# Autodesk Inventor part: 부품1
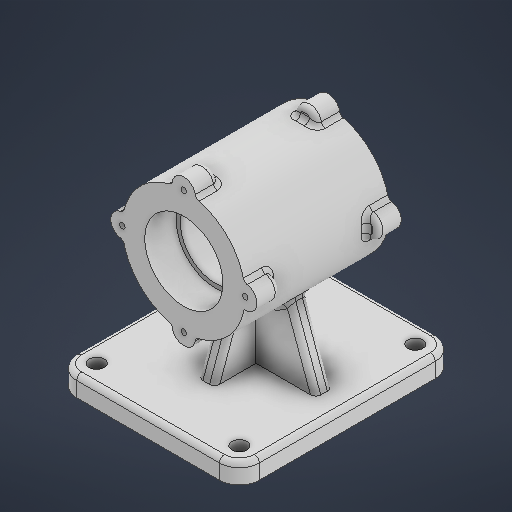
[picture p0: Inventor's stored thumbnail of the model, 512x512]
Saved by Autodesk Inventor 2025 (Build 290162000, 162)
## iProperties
Created: 2025-08
Part Number: 부품1
Material: 일반
Document SubType Name: Modeling
Designer: infra023
Density: 1 g/cm^3
Appearance: 기본값
Author: infra023
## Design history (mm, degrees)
sketch "스케치1"
  geometry: L1 (55, 65)-(-55, 65); L2 (-55, 65)-(-55, -65); L3 (-55, -65)-(55, -65); L4 (55, -65)-(55, 65); 3 further points
  constraints: 8 end point, 2 midpoint, 2 parallel, 1 horizontal, 1 horizontal alignment, 1 perpendicular, 1 vertical alignment
  dimensions: "d0" = 130 distance of L3.end L1.start; "d1" = 110 distance of L2.end L3.end
extrude "돌출1" new body sketch "스케치1" distance "d2" = 12; taper "d3" = 0 deg
fillet "모깎기1" dims "d4" = 12
sketch "스케치2"
  geometry: L1 (43, 53)-(-43, 53); L2 (-43, 53)-(-43, -53); L3 (-43, -53)-(43, -53); L4 (43, -53)-(43, 53); 3 further points
  constraints: 8 end point, 2 midpoint, 2 parallel, 1 horizontal, 1 horizontal alignment, 1 perpendicular, 1 vertical alignment
  dimensions: "d5" = 106 distance of L1.end L2.end; "d6" = 86 distance of L2.end L3.end
hole "구멍1" sketch "스케치2" at (43, 53), (43, -53), (-43, -53), (-43, 53) diameter "d7" = 9; stored, may be unused: countersink angle "d11" = 90 deg, drill point angle "d13" = 118 deg; dims "d8" = 6, "d9" = 4, "d10" = 2, "d12" = 8
sketch "스케치3"
  geometry: L1 (-12, -53)-(-12, 53) reference; L2 (-12, 0)-(70, 0); L3 (70, 0)-(70, -43.5); L4 (70, -43.5)-(107, -43.5); L5 (107, -43.5)-(107, 43.5); L6 (107, 43.5)-(70, 43.5); L7 (70, 0)-(70, 43.5); L8 (70, -43.5)-(91, -43.5); L9 (91, -24.5)-(91, 24.5); L10 (70, -43.5)-(93.5, -43.5); L11 (93.5, -43.5)-(93.5, -24.5); L12 (93.5, -24.5)-(70, -24.5); L13 (93.5, 43.5)-(93.5, 24.5); L14 (93.5, 24.5)-(70, 24.5); 2 further points
  constraints: 26 end point, 5 perpendicular, 5 point on line, 3 symmetric about line, 2 parallel, 1 horizontal, 1 midpoint, 1 vertical
  dimensions: "d14" = 82 distance of L2.start L2.end; "d15" = 43.5 distance of L2.end L3.end; "d16" = 37 distance of L3.end L4.end; "d17" = 87 distance of L4.end L5.end; "d18" = 21 distance of L3.end L8.end; "d19" = 23.5 distance of L3.end L10.end; "d20" = 19 distance of L10.end L11.end; "d21" = 16 distance between parallel lines of L5 L9
revolve "회전1" sketch "스케치3" stored, may be unused: angle "d22" = 90 deg
sketch "스케치4"
  geometry: L1 (0, 0)-(0, 37); L2 (0, 0)-(-37, 0); L3 (0, 0)-(37, 0); L4 (0, 0)-(0, -37); C1 r 21 at (0, 0) reference; C2 r 7 at (37, 0); C3 r 7 at (-37, 0); C4 r 7 at (0, 37); C5 r 7 at (0, -37); A1 r 37 centre (0, 0) between (0, 37) and (-37, 0) reference; 3 further points
  constraints: 8 end point, 4 centre point, 4 coincident, 4 point on circle, 2 horizontal, 2 vertical
  dimensions: "d23" = 14 diameter of C2; "d24" = 14 diameter of C3; "d25" = 14 diameter of C4; "d26" = 14 diameter of C5
sketch "스케치5"
  geometry: C1 r 7 at (0, 37) reference; C2 r 7 at (-37, 0) reference; C3 r 7 at (37, 0) reference; C4 r 7 at (0, -37) reference; 1 further point
extrude "돌출2" join sketch "스케치4" distance "d27" = 14; taper "d28" = 0 deg
extrude "돌출3" join sketch "스케치5" distance "d29" = 14; taper "d30" = 0 deg
fillet "모깎기2" dims "d31" = 3
fillet "모깎기3" dims "d32" = 3
fillet "모깎기4" dims "d33" = 3
sketch "스케치6"
  geometry: L1 (-37, -37)-(0, -37); C1 r 7 at (-37, -37); A1 r 7 centre (-37, -37) between (-38.239, -30.111) and (-38.239, -43.889) reference; A2 r 40 centre (0, -37) between (-39.905, -34.251) and (-39.905, -39.749) reference; 3 further points
  constraints: 2 end point, 1 centre point, 1 coincident, 1 concentric, 1 horizontal
extrude "돌출4" join sketch "스케치6" distance "d34" = 14; taper "d35" = 0 deg
fillet "모깎기5" dims "d36" = 3
sketch "스케치7"
  geometry: L1 (0, 37)-(-37, 37); L2 (0, 37)-(0, 74); L3 (0, 37)-(37, 37); L4 (0, 37)-(0, 0); C1 r 23.5 at (0, 37) reference; C2 r 37 at (0, 37); 1 further point
  constraints: 8 end point, 2 horizontal, 2 vertical, 1 centre point, 1 coincident
  dimensions: "d37" = 74 diameter of C2; "d38" = 37 distance of L1.start L1.end; "d39" = 37 distance of L1.start L2.end; "d40" = 37 distance of L1.start L3.end; "d41" = 37 distance of L1.start L4.end
hole "구멍2" sketch "스케치7" at (0, 74), (-37, 37), (37, 37), (0, 0) diameter "d42" = 3.242; stored, may be unused: countersink angle "d46" = 90 deg, drill point angle "d48" = 118 deg; dims "d43" = 8, "d44" = 4, "d45" = 2, "d47" = 10
sketch "스케치8"
  geometry: C1 r 1.621 at (0, 0) reference; C2 r 1.621 at (37, -37) reference; C3 r 1.621 at (-37, -37) reference; C4 r 1.621 at (0, -74) reference; 1 further point
hole "구멍3" sketch "스케치8" at (0, 0), (-37, -37), (37, -37), (0, -74) diameter "d49" = 3.242; stored, may be unused: countersink angle "d53" = 90 deg, drill point angle "d55" = 118 deg; dims "d50" = 8, "d51" = 4, "d52" = 2, "d54" = 10
sketch "스케치9"
  geometry: L1 (0, 0)-(0, 30); L2 (0, -53)-(0, 53) reference; L3 (0, 0)-(0, -30); L4 (0, 30)-(40, 15.441); L5 (0, 30)-(53.209, 30); L6 (0, -30)-(33, -17.989); L7 (0, -30)-(44.695, -30); L8 (0, 0)-(63, 0); L9 (33, -26.5)-(33, 26.5) reference; L10 (33, 0)-(33, 22); L11 (33, 0)-(33, -22.357); L12 (33, -17.989)-(40, -15.441); L13 (40, -15.441)-(40, 15.441); 1 further point
  constraints: 22 end point, 5 point on line, 3 horizontal, 1 midpoint, 1 vertical
  dimensions: "d56" = 30 distance of L1.start L1.end; "d57" = 30 distance of L1.start L3.end; "d58" = 20 deg angle of L4 L5; "d59" = 20 deg angle of L7 L6; "d71" = 70 deg angle of L12 L9; "d72" = 7 distance between parallel lines of L13 L9; "d73" = 30 distance from line of L8.end L9; "d74" = 37.57735 distance from line of L10.end L12; "d75" = 4.10424 distance from line of L11.end L12
sketch "스케치10"
  geometry: L1 (-43, -3)-(-55, -3) reference; L2 (-55, -3)-(-41, -3); L3 (43, -3)-(-43, -3) reference; L4 (-41, -3)-(-41, 0); L5 (-43, 0)-(-41, 0); L6 (-47.5, 0)-(-38.5, 0) reference; L7 (-41, 0)-(-24.257, 46); L8 (-41, 0)-(7.952, 0); L9 (43, -12)-(-43, -12) reference; L10 (0, -12)-(0, 22); L11 (41, 0)-(24.257, 46); L12 (-41, 0)-(41, 0); L13 (43, 0)-(-43, 0) reference; 1 further point
  constraints: 16 end point, 2 collinear, 2 point on line, 2 symmetric about line, 1 equal length, 1 horizontal, 1 midpoint, 1 perpendicular, 1 vertical
  dimensions: "d62" = 14 distance of L1.end L2.end; "d63" = 70 deg angle of L8 L7
feature "리브1" sketch "스케치10" dims "d64" = 1, "d65" = 10, "d66" = 0, "d67" = 0, "d68" = 1, "d69" = 1
fillet "모깎기6" dims "d70" = 3
extrude "돌출6" join sketch "스케치9" stored distance "d76" = 10; taper "d77" = 0 deg
fillet "모깎기7" dims "d78" = 3
fillet "모깎기8" dims "d79" = 3
fillet "모깎기9" dims "d80" = 3
node "솔리드1"
feature "A9D066F2-1C7D-4E18-AEED-F7BC21143FA4" dims "d7" = 9, "d8" = 6, "d9" = 4, "d10" = 2, "d11" = 90 deg, "d12" = 8, "d13" = 118 deg
